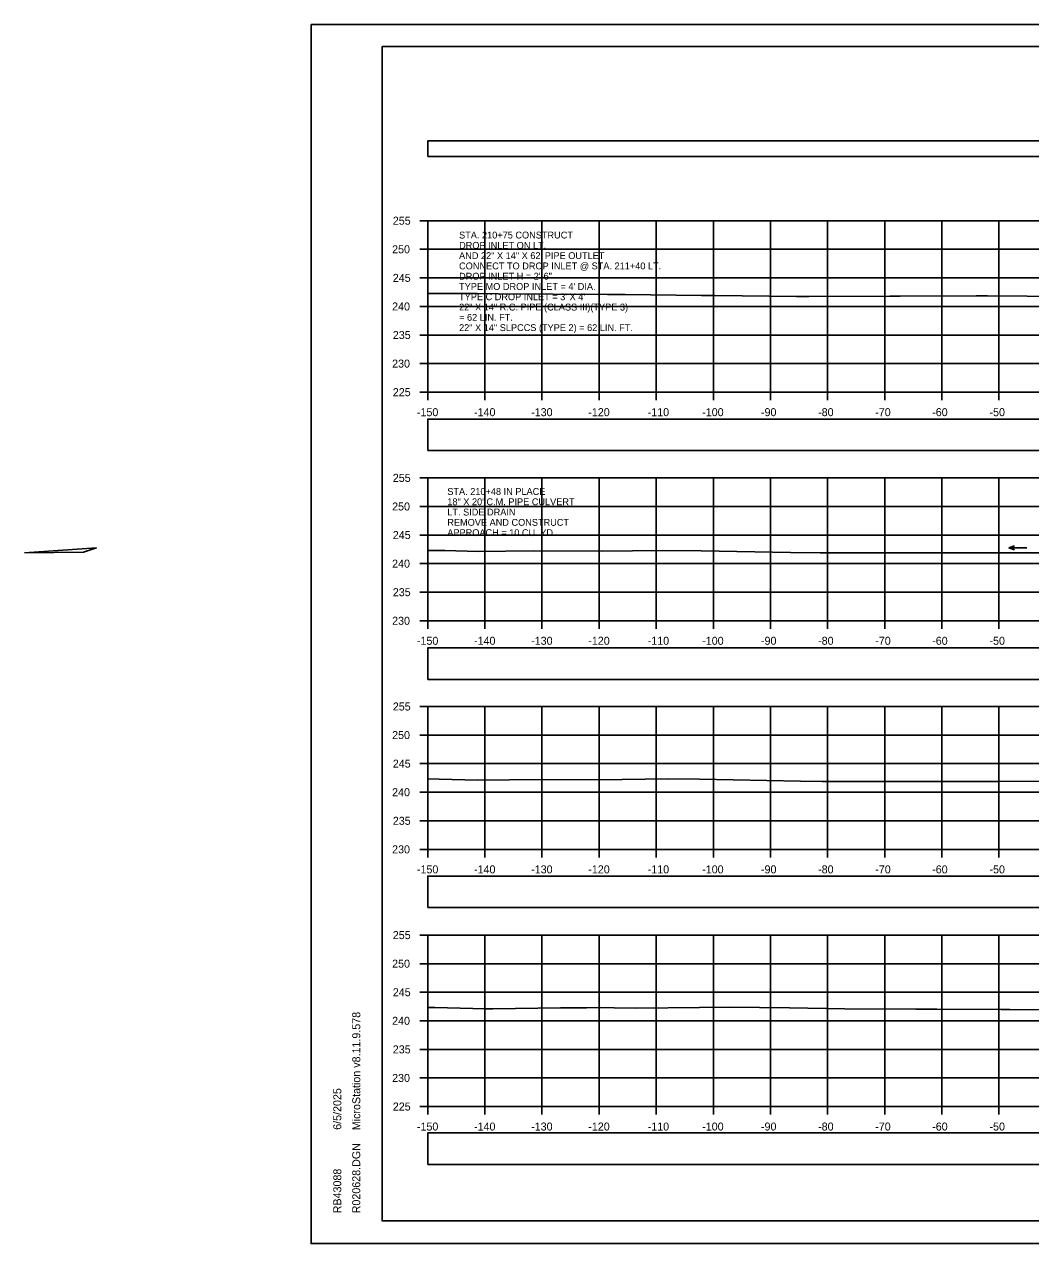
# Model space of a CAD drawing. Extents: x 1369627 to 1374022, y 380035 to 398173.
# Drawn here: x 1371877.9 to 1372054.1, y 382172.2 to 382385.5 of the extents above; entities that cross this region are included whole.
import ezdxf

# ---------------------------------------------------------------- set-up
doc = ezdxf.new("R2010")
doc.units = 0
for name, color, linetype in [('Default', 7, 'Continuous'), ('R_Axis', 7, 'Continuous'), ('R_Axis Annot', 7, 'Continuous'), ('R_Border', 7, 'Continuous'), ('R_Drive', 7, 'Continuous'), ('R_Exist Surface', 7, 'Continuous'), ('R_Grid', 7, 'Continuous'), ('R_No Plot', 7, 'Continuous'), ('R_Water', 7, 'Continuous'), ('R_Water Annot', 7, 'Continuous')]:
    doc.layers.add(name, color=color, linetype=linetype)

msp = doc.modelspace()

# ---------------------------------------------------------------- linework, layer by layer
at = {"layer": 'Default'}
for points in [[(1371948.53, 382362.4), (1372248.53, 382362.4), (1372248.53, 382365.11), (1371948.53, 382365.11)], [(1371948.53, 382310.92), (1372248.53, 382310.92), (1372248.53, 382316.44), (1371948.53, 382316.44)], [(1371948.53, 382270.87), (1372248.53, 382270.87), (1372248.53, 382276.39), (1371948.53, 382276.39)], [(1371948.53, 382230.95), (1372248.53, 382230.95), (1372248.53, 382236.47), (1371948.53, 382236.47)], [(1371948.53, 382186), (1372248.53, 382186), (1372248.53, 382191.52), (1371948.53, 382191.52)]]:
    msp.add_lwpolyline(points, close=True, dxfattribs=at)
at = {"layer": 'R_Axis'}
for p, q in [((1371947.13, 382351.14), (1371948.53, 382351.14)), ((1371948.53, 382321.14), (1371948.53, 382351.14)), ((1371947.13, 382346.14), (1371948.53, 382346.14)), ((1371947.13, 382341.14), (1371948.53, 382341.14)), ((1371947.13, 382336.14), (1371948.53, 382336.14)), ((1371947.13, 382331.14), (1371948.53, 382331.14)), ((1371947.13, 382326.14), (1371948.53, 382326.14)), ((1371947.13, 382321.14), (1371948.53, 382321.14)), ((1371948.53, 382321.14), (1372248.53, 382321.14)), ((1371948.53, 382319.74), (1371948.53, 382321.14)), ((1371958.53, 382319.74), (1371958.53, 382321.14)), ((1371968.53, 382319.74), (1371968.53, 382321.14)), ((1371978.53, 382319.74), (1371978.53, 382321.14)), ((1371988.53, 382319.74), (1371988.53, 382321.14)), ((1371998.53, 382319.74), (1371998.53, 382321.14)), ((1372008.53, 382319.74), (1372008.53, 382321.14)), ((1372018.53, 382319.74), (1372018.53, 382321.14)), ((1372028.53, 382319.74), (1372028.53, 382321.14)), ((1372038.53, 382319.74), (1372038.53, 382321.14)), ((1372048.53, 382319.74), (1372048.53, 382321.14)), ((1371947.13, 382306.14), (1371948.53, 382306.14)), ((1371948.53, 382281.14), (1371948.53, 382306.14)), ((1371947.13, 382301.14), (1371948.53, 382301.14)), ((1371947.13, 382296.14), (1371948.53, 382296.14)), ((1371947.13, 382291.14), (1371948.53, 382291.14)), ((1371947.13, 382286.14), (1371948.53, 382286.14)), ((1371947.13, 382281.14), (1371948.53, 382281.14)), ((1371948.53, 382281.14), (1372248.53, 382281.14)), ((1371948.53, 382279.74), (1371948.53, 382281.14)), ((1371958.53, 382279.74), (1371958.53, 382281.14)), ((1371968.53, 382279.74), (1371968.53, 382281.14)), ((1371978.53, 382279.74), (1371978.53, 382281.14)), ((1371988.53, 382279.74), (1371988.53, 382281.14)), ((1371998.53, 382279.74), (1371998.53, 382281.14)), ((1372008.53, 382279.74), (1372008.53, 382281.14)), ((1372018.53, 382279.74), (1372018.53, 382281.14)), ((1372028.53, 382279.74), (1372028.53, 382281.14)), ((1372038.53, 382279.74), (1372038.53, 382281.14)), ((1372048.53, 382279.74), (1372048.53, 382281.14)), ((1371947.13, 382266.14), (1371948.53, 382266.14)), ((1371948.53, 382241.14), (1371948.53, 382266.14)), ((1371947.13, 382261.14), (1371948.53, 382261.14)), ((1371947.13, 382256.14), (1371948.53, 382256.14)), ((1371947.13, 382251.14), (1371948.53, 382251.14)), ((1371947.13, 382246.14), (1371948.53, 382246.14)), ((1371947.13, 382241.14), (1371948.53, 382241.14)), ((1371948.53, 382241.14), (1372248.53, 382241.14)), ((1371948.53, 382239.74), (1371948.53, 382241.14)), ((1371958.53, 382239.74), (1371958.53, 382241.14)), ((1371968.53, 382239.74), (1371968.53, 382241.14)), ((1371978.53, 382239.74), (1371978.53, 382241.14)), ((1371988.53, 382239.74), (1371988.53, 382241.14)), ((1371998.53, 382239.74), (1371998.53, 382241.14)), ((1372008.53, 382239.74), (1372008.53, 382241.14)), ((1372018.53, 382239.74), (1372018.53, 382241.14)), ((1372028.53, 382239.74), (1372028.53, 382241.14)), ((1372038.53, 382239.74), (1372038.53, 382241.14)), ((1372048.53, 382239.74), (1372048.53, 382241.14)), ((1371947.13, 382226.14), (1371948.53, 382226.14)), ((1371948.53, 382196.14), (1371948.53, 382226.14)), ((1371947.13, 382221.14), (1371948.53, 382221.14)), ((1371947.13, 382216.14), (1371948.53, 382216.14)), ((1371947.13, 382211.14), (1371948.53, 382211.14)), ((1371947.13, 382206.14), (1371948.53, 382206.14)), ((1371947.13, 382201.14), (1371948.53, 382201.14)), ((1371947.13, 382196.14), (1371948.53, 382196.14)), ((1371948.53, 382196.14), (1372248.53, 382196.14)), ((1371948.53, 382194.74), (1371948.53, 382196.14)), ((1371958.53, 382194.74), (1371958.53, 382196.14)), ((1371968.53, 382194.74), (1371968.53, 382196.14)), ((1371978.53, 382194.74), (1371978.53, 382196.14)), ((1371988.53, 382194.74), (1371988.53, 382196.14)), ((1371998.53, 382194.74), (1371998.53, 382196.14)), ((1372008.53, 382194.74), (1372008.53, 382196.14)), ((1372018.53, 382194.74), (1372018.53, 382196.14)), ((1372028.53, 382194.74), (1372028.53, 382196.14)), ((1372038.53, 382194.74), (1372038.53, 382196.14)), ((1372048.53, 382194.74), (1372048.53, 382196.14))]:
    msp.add_line(p, q, dxfattribs=at)
at = {"layer": 'R_Border'}
for p, q in [((1371940.53, 382381.6), (1372256.71, 382381.6)), ((1371940.53, 382176.14), (1371940.53, 382381.6)), ((1371940.53, 382176.14), (1371940.53, 382176.14)), ((1372256.71, 382176.14), (1371940.53, 382176.14))]:
    msp.add_line(p, q, dxfattribs=at)
at = {"layer": 'R_Drive'}
for p, q in [((1371890.54, 382293.88), (1371877.92, 382293.05)), ((1371877.92, 382293.05), (1371888.27, 382293.13)), ((1371888.27, 382293.13), (1371890.54, 382293.88))]:
    msp.add_line(p, q, dxfattribs=at)
at = {"layer": 'R_Exist Surface'}
for points in [[(1371948.53, 382338.43), (1371953.49, 382338.4), (1371957.17, 382338.38), (1371960.88, 382338.36), (1371980, 382338.23), (1371983.1, 382338.21), (1371996.45, 382338.06), (1371998.81, 382338.05), (1372013.11, 382337.88), (1372015.26, 382337.88), (1372029.42, 382337.93), (1372029.68, 382337.93), (1372031.23, 382337.94), (1372044.53, 382337.99), (1372046.51, 382338), (1372053.47, 382337.95), (1372070.8, 382337.86)], [(1371948.53, 382293.46), (1371951.55, 382293.44), (1371957.36, 382293.28), (1371967.01, 382293.39), (1371979.04, 382293.31), (1371989.69, 382293.46), (1371996.41, 382293.39), (1372012.01, 382293.07), (1372017.25, 382293.01), (1372028.29, 382293.01), (1372031.77, 382293.02), (1372044.27, 382293), (1372046.13, 382293.01), (1372056.63, 382293.03)], [(1371948.53, 382253.46), (1371950.53, 382253.44), (1371957.27, 382253.25), (1371968.43, 382253.39), (1371978.51, 382253.32), (1371990.7, 382253.49), (1371996.11, 382253.43), (1372013.79, 382253.07), (1372017.58, 382253.03), (1372029.98, 382253.02), (1372032.02, 382253.03), (1372045.92, 382253.01), (1372046.31, 382253.02), (1372048.49, 382253.02), (1372074.3, 382253.21)], [(1371948.53, 382213.45), (1371949.1, 382213.45), (1371949.77, 382213.45), (1371958.63, 382213.22), (1371959.91, 382213.22), (1371971.8, 382213.39), (1371976.3, 382213.41), (1371978.85, 382213.46), (1371981.14, 382213.4), (1371985.05, 382213.35), (1371996.1, 382213.48), (1372001.34, 382213.5), (1372011.84, 382213.42), (1372021.57, 382213.22), (1372033.96, 382213.17), (1372037.66, 382213.16), (1372048.92, 382213.1), (1372050.44, 382213.1), (1372058.71, 382213.08)]]:
    msp.add_lwpolyline(points, dxfattribs=at)
at = {"layer": 'R_Grid'}
for p, q in [((1371948.53, 382351.14), (1372248.53, 382351.14)), ((1371948.53, 382321.14), (1371948.53, 382351.14)), ((1371958.53, 382321.14), (1371958.53, 382351.14)), ((1371968.53, 382321.14), (1371968.53, 382351.14)), ((1371978.53, 382321.14), (1371978.53, 382351.14)), ((1371988.53, 382321.14), (1371988.53, 382351.14)), ((1371998.53, 382321.14), (1371998.53, 382351.14)), ((1372008.53, 382321.14), (1372008.53, 382351.14)), ((1372018.53, 382321.14), (1372018.53, 382351.14)), ((1372028.53, 382321.14), (1372028.53, 382351.14)), ((1372038.53, 382321.14), (1372038.53, 382351.14)), ((1372048.53, 382321.14), (1372048.53, 382351.14)), ((1371948.53, 382346.14), (1372248.53, 382346.14)), ((1371948.53, 382341.14), (1372248.53, 382341.14)), ((1371948.53, 382336.14), (1372248.53, 382336.14)), ((1371948.53, 382331.14), (1372248.53, 382331.14)), ((1371948.53, 382326.14), (1372248.53, 382326.14)), ((1371948.53, 382321.14), (1372248.53, 382321.14)), ((1371948.53, 382306.14), (1372248.53, 382306.14)), ((1371948.53, 382281.14), (1371948.53, 382306.14)), ((1371958.53, 382281.14), (1371958.53, 382306.14)), ((1371968.53, 382281.14), (1371968.53, 382306.14)), ((1371978.53, 382281.14), (1371978.53, 382306.14)), ((1371988.53, 382281.14), (1371988.53, 382306.14)), ((1371998.53, 382281.14), (1371998.53, 382306.14)), ((1372008.53, 382281.14), (1372008.53, 382306.14)), ((1372018.53, 382281.14), (1372018.53, 382306.14)), ((1372028.53, 382281.14), (1372028.53, 382306.14)), ((1372038.53, 382281.14), (1372038.53, 382306.14)), ((1372048.53, 382281.14), (1372048.53, 382306.14)), ((1371948.53, 382301.14), (1372248.53, 382301.14)), ((1371948.53, 382296.14), (1372248.53, 382296.14)), ((1371948.53, 382291.14), (1372248.53, 382291.14)), ((1371948.53, 382286.14), (1372248.53, 382286.14)), ((1371948.53, 382281.14), (1372248.53, 382281.14)), ((1371948.53, 382266.14), (1372248.53, 382266.14)), ((1371948.53, 382241.14), (1371948.53, 382266.14)), ((1371958.53, 382241.14), (1371958.53, 382266.14)), ((1371968.53, 382241.14), (1371968.53, 382266.14)), ((1371978.53, 382241.14), (1371978.53, 382266.14)), ((1371988.53, 382241.14), (1371988.53, 382266.14)), ((1371998.53, 382241.14), (1371998.53, 382266.14)), ((1372008.53, 382241.14), (1372008.53, 382266.14)), ((1372018.53, 382241.14), (1372018.53, 382266.14)), ((1372028.53, 382241.14), (1372028.53, 382266.14)), ((1372038.53, 382241.14), (1372038.53, 382266.14)), ((1372048.53, 382241.14), (1372048.53, 382266.14)), ((1371948.53, 382261.14), (1372248.53, 382261.14)), ((1371948.53, 382256.14), (1372248.53, 382256.14)), ((1371948.53, 382251.14), (1372248.53, 382251.14)), ((1371948.53, 382246.14), (1372248.53, 382246.14)), ((1371948.53, 382241.14), (1372248.53, 382241.14)), ((1371948.53, 382226.14), (1372248.53, 382226.14)), ((1371948.53, 382196.14), (1371948.53, 382226.14)), ((1371958.53, 382196.14), (1371958.53, 382226.14)), ((1371968.53, 382196.14), (1371968.53, 382226.14)), ((1371978.53, 382196.14), (1371978.53, 382226.14)), ((1371988.53, 382196.14), (1371988.53, 382226.14)), ((1371998.53, 382196.14), (1371998.53, 382226.14)), ((1372008.53, 382196.14), (1372008.53, 382226.14)), ((1372018.53, 382196.14), (1372018.53, 382226.14)), ((1372028.53, 382196.14), (1372028.53, 382226.14)), ((1372038.53, 382196.14), (1372038.53, 382226.14)), ((1372048.53, 382196.14), (1372048.53, 382226.14)), ((1371948.53, 382221.14), (1372248.53, 382221.14)), ((1371948.53, 382216.14), (1372248.53, 382216.14)), ((1371948.53, 382211.14), (1372248.53, 382211.14)), ((1371948.53, 382206.14), (1372248.53, 382206.14)), ((1371948.53, 382201.14), (1372248.53, 382201.14)), ((1371948.53, 382196.14), (1372248.53, 382196.14))]:
    msp.add_line(p, q, dxfattribs=at)
at = {"layer": 'R_No Plot'}
for p, q in [((1371928.13, 382385.49), (1372261.46, 382385.49)), ((1371928.13, 382172.16), (1372261.46, 382172.16))]:
    msp.add_line(p, q, dxfattribs=at)
for points in [[(1371928.12, 382385.49), (1372261.46, 382385.49), (1372261.46, 382172.16), (1371928.12, 382172.16)], [(1372174.45, 382381.6), (1372194.07, 382381.6), (1372194.07, 382371.72), (1372210.18, 382371.72), (1372233.38, 382371.72), (1372233.38, 382339.05), (1372256.59, 382339.05), (1372256.71, 382176.14), (1371940.53, 382176.14), (1371940.53, 382381.6)]]:
    msp.add_lwpolyline(points, close=True, dxfattribs=at)
at = {"layer": 'R_Water Annot'}
for p, q in [((1372050.28, 382293.89), (1372051.24, 382294.24)), ((1372053.42, 382293.89), (1372050.28, 382293.89)), ((1372050.28, 382293.89), (1372051.24, 382293.54))]:
    msp.add_line(p, q, dxfattribs=at)

# ---------------------------------------------------------------- texts
at = {"layer": 'R_Axis Annot'}
for s, p in [('255', (1371942.42, 382350.44)), ('250', (1371942.3, 382345.44)), ('245', (1371942.42, 382340.44)), ('240', (1371942.3, 382335.44)), ('235', (1371942.42, 382330.44)), ('230', (1371942.3, 382325.44)), ('225', (1371942.42, 382320.44)), ('-150', (1371946.64, 382316.94)), ('-140', (1371956.64, 382316.94)), ('-130', (1371966.64, 382316.94)), ('-120', (1371976.64, 382316.94)), ('-110', (1371987.04, 382316.94)), ('-100', (1371996.58, 382316.94)), ('-90', (1372006.87, 382316.94)), ('-80', (1372016.87, 382316.94)), ('-70', (1372026.87, 382316.94)), ('-60', (1372036.84, 382316.94)), ('-50', (1372046.87, 382316.94)), ('255', (1371942.42, 382305.44)), ('250', (1371942.3, 382300.44)), ('245', (1371942.42, 382295.44)), ('240', (1371942.3, 382290.44)), ('235', (1371942.42, 382285.44)), ('230', (1371942.3, 382280.44)), ('-150', (1371946.64, 382276.94)), ('-140', (1371956.64, 382276.94)), ('-130', (1371966.64, 382276.94)), ('-120', (1371976.64, 382276.94)), ('-110', (1371987.04, 382276.94)), ('-100', (1371996.58, 382276.94)), ('-90', (1372006.87, 382276.94)), ('-80', (1372016.87, 382276.94)), ('-70', (1372026.87, 382276.94)), ('-60', (1372036.84, 382276.94)), ('-50', (1372046.87, 382276.94)), ('255', (1371942.42, 382265.44)), ('250', (1371942.3, 382260.44)), ('245', (1371942.42, 382255.44)), ('240', (1371942.3, 382250.44)), ('235', (1371942.42, 382245.44)), ('230', (1371942.3, 382240.44)), ('-150', (1371946.64, 382236.94)), ('-140', (1371956.64, 382236.94)), ('-130', (1371966.64, 382236.94)), ('-120', (1371976.64, 382236.94)), ('-110', (1371987.04, 382236.94)), ('-100', (1371996.58, 382236.94)), ('-90', (1372006.87, 382236.94)), ('-80', (1372016.87, 382236.94)), ('-70', (1372026.87, 382236.94)), ('-60', (1372036.84, 382236.94)), ('-50', (1372046.87, 382236.94)), ('255', (1371942.42, 382225.44)), ('250', (1371942.3, 382220.44)), ('245', (1371942.42, 382215.44)), ('240', (1371942.3, 382210.44)), ('235', (1371942.42, 382205.44)), ('230', (1371942.3, 382200.44)), ('225', (1371942.42, 382195.44)), ('-150', (1371946.64, 382191.94)), ('-140', (1371956.64, 382191.94)), ('-130', (1371966.64, 382191.94)), ('-120', (1371976.64, 382191.94)), ('-110', (1371987.04, 382191.94)), ('-100', (1371996.58, 382191.94)), ('-90', (1372006.87, 382191.94)), ('-80', (1372016.87, 382191.94)), ('-70', (1372026.87, 382191.94)), ('-60', (1372036.84, 382191.94)), ('-50', (1372046.87, 382191.94))]:
    msp.add_text(s, height=1.4, dxfattribs=at).set_placement(p)
at = {"layer": 'R_Border'}
for s, p in [('MicroStation v8.11.9.578', (1371936.72, 382192)), ('6/5/2025', (1371933.4, 382192.07)), ('R020628.DGN', (1371936.72, 382177.46)), ('RB43088', (1371933.4, 382177.46))]:
    msp.add_text(s, height=1.4, rotation=90, dxfattribs=at).set_placement(p)
at = {"layer": 'R_Water'}
for s, p in [('STA. 210+48 IN PLACE', (1371951.96, 382303.16)), ('18" X 20\' C.M. PIPE CULVERT', (1371951.96, 382301.36)), ('LT. SIDE DRAIN', (1371951.96, 382299.56)), ('REMOVE AND CONSTRUCT', (1371951.96, 382297.76)), ('APPROACH = 10 CU. YD.', (1371951.96, 382295.96))]:
    msp.add_text(s, height=1.2, dxfattribs=at).set_placement(p)
at = {"layer": 'R_Water Annot'}
for s, p in [('STA. 210+75 CONSTRUCT', (1371954.02, 382348.03)), ('DROP INLET ON LT.', (1371954.02, 382346.23)), ('AND 22" X 14" X 62\' PIPE OUTLET', (1371954.02, 382344.43)), ('CONNECT TO DROP INLET @ STA. 211+40 LT.', (1371954.02, 382342.63)), ('DROP INLET H = 2\'-6"', (1371954.02, 382340.83)), ("TYPE MO DROP INLET = 4' DIA.", (1371954.02, 382339.03)), ("TYPE C DROP INLET = 3' X 4'", (1371954.02, 382337.23)), ('22" X 14" R.C. PIPE (CLASS III)(TYPE 3)', (1371954.02, 382335.43)), ('= 62 LIN. FT.', (1371954.02, 382333.63)), ('22" X 14" SLPCCS (TYPE 2) = 62 LIN. FT.', (1371954.02, 382331.83))]:
    msp.add_text(s, height=1.2, dxfattribs=at).set_placement(p)

doc.saveas('drawing.dxf')
